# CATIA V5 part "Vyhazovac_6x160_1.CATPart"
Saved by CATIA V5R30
Part number: Vyhazovac_6x160_1
Nomenclature: E1710/6x160
Description: MEUSBURGER
Property "Material": "1.221"
Publications: "__DrillHole", "Base"
Bounding box of the stored display mesh (mm): x -5.992 to 5.992, y -5.992 to 5.992, z 0 to 156.5
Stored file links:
  E:\Bakalarka\Model\Forma_v7\Vyhazovac_6x160_1.CATPart
  E:\dev\MoldDesign\intel_a\startup\components\MoldCatalog\Ejector\Meusburger\Ejector_E1710\TableE1710.txt
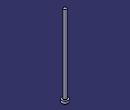
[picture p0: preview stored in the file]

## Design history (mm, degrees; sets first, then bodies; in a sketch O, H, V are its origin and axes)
Parameters
  Ref = "E1710/6x160" {design table}
  D1 = 6 mm {design table}
  D3 = 12 mm {design table}
  L = 160 mm {design table}
  L3 = 5 mm {design table}
  R = 0.5 mm {design table}
  k_d3 = 13 mm {design table}
  k_d1 = 6.2 mm {design table}
  k_F = 0.5 mm {design table}
  kl = 17 mm {design table}
  Mat = "1.221" {design table}
  HeatTreat = "ISO6751" {design table}
  Offset_Parting = 10 mm
  Anti_Rotation = "Normal"
  Anti_Rotation_D = 3.5 mm
  Anti_Rotation_D_Icut = 3.5 mm
  Add_Length_L = 1.8377 mm
  Add_Length_D3 = 0 mm
  SupplierRef = "Meusburger 2017"
  BmpRef = "F_MldEjectorD1"
  DrillHole_Length = 225 mm
  ValidationTest = false
  Anti_Rotation_D_min = 3.5 mm {= OffSet_D1 /2}
  Anti_Rotation_D_max = 5.925 mm {= D3/2-0.075mm}
  Anti_Rotation_D_ref = 3.5 mm {= Anti_Rotation_D}
  Anti_Rotation_D_Icut_ref = 3.5 mm {= Anti_Rotation_D_Icut}
  Anti_Rotation_Ref_Icut = 2.3246 mm
  Offset_L = 20 mm
  D = 6 mm {= D1}
  OffSet_D1 = 7 mm {= D1+2*R}
  OffSet_D3 = 13 mm {= D3+1mm}
  XG_Split = -80 mm
  YG_Split = -12 mm
  ZG_Split = -198 mm
  DirX_Split = 0 mm
  DirY_Split = 0 mm
  DirZ_Split = 1 mm
Set1 "BaseBody"
  Point1 "Base": (0, 0, 0)
  Plane1: type Offset, RefPlane xy-plane, Offset 225 {= DrillHole_Length}, reversed
  Sketch1 "Sketch.2" on xy-plane, origin (0, 0, 0), H (1, 0, 0), V (0, 1, 0)
    point P1 (-0.46, 1.1623)
    point P2 (0.46, 1.1623)
    construction line L1 (-0.46, 1.1623) -> (0.46, 1.1623)
    point P3 (0.46, -1.1623)
    line L2 (0.46, -1.1623) -> (0.46, 1.1623)
    point P4 (-0.46, -1.1623)
    construction line L3 (0.46, -1.1623) -> (-0.46, -1.1623)
    line L4 (-0.46, 1.1623) -> (-0.46, -1.1623)
    point P5 (-0.21, 1.1623)
    arc A1 centre (-0.21, 1.1623) radius 0.25 from (-0.21, 1.4123) to (-0.46, 1.1623) ccw
    point P7 (0.21, 1.1623)
    point P8 (0.21, 1.4123)
    arc A2 centre (0.21, 1.1623) radius 0.25 from (0.46, 1.1623) to (0.21, 1.4123) ccw
    line L5 (-0.21, 1.4123) -> (0.21, 1.4123)
    point P9 (-0.46, -1.1623)
    arc A3 centre (-0.21, -1.1623) radius 0.25 from (-0.46, -1.1623) to (-0.21, -1.4123) ccw
    point P11 (0.21, -1.4123)
    line L6 (-0.21, -1.4123) -> (0.21, -1.4123)
    point P12 (0.46, -1.1623)
    arc A4 centre (0.21, -1.1623) radius 0.25 from (0.21, -1.4123) to (0.46, -1.1623) ccw
    point P14 (-0.46, 1.1623)
    point P15 (-0.46, -1.1623)
    point P16 (0.46, 1.1623)
    point P17 (0.46, -1.1623)
    reference projected circle E1 centre (0, 0) radius 1.25 from edge [face of Shaft1 from Sketch2.L3 | face of Shaft1 from Sketch2.L4]
    reference projected circle E2 centre (0, 0) radius 1.25 from edge [face of Shaft1 from Sketch2.L3 | face of Shaft1 from Sketch2.L4]
    reference projected circle E3 centre (0, 0) radius 1.25 from edge [face of Shaft1 from Sketch2.L3 | face of Shaft1 from Sketch2.L4]
    reference projected circle E4 centre (0, 0) radius 1.25 from edge [face of Shaft1 from Sketch2.L3 | face of Shaft1 from Sketch2.L4]
    point P18 (-0.46, -1.1623)
    point P19 (-0.21, -1.4123)
    point P20 (0.21, -1.4123)
    point P21 (0.46, -1.1623)
    point P22 (-0.21, -1.4123)
    point P23 (0.21, -1.4123)
    distance P14 P15 = 2.3246 (reference)
    distance P16 P17 = 2.3246 (reference)
    distance L1 P14 = 0 (reference)
    radius A1 = 3
    distance L4 V = 3.51
    distance L2 V = 5.935
    distance L5 L6 = 12
    horizontal: L1 H, L3 H, L5 H
    vertical: L2 V, L4 V
    coincidence: P5 L1, P7 L1, P3 P12, P14 L4, P15 L4, P16 L2, P17 L2, P14 E1, P15 E2, P16 E3, P17 E4, P3 P21, P4 P18, P20 P23, P19 P22
    tangency: A1 L4, A2 L2, A2 L5, A1 L5
    symmetry: P1 P9 H, A1 A3 H, P8 P11 H, L5 L6 H, P2 P12 H, A2 A4 H
  DatumSurface1
Body1 "PartBody" (main body)
  Sketch2 "Sketch.1" on zx-plane, origin (0, 0, 0), H (-1, 0, 0), V (0, 0, 1)
    point P1 (0, 160)
    line L1 (3, 160) -> (0, 160)
    line L2 (3, 5) -> (3, 160)
    line L3 (6, 5) -> (3, 5)
    line L4 (6, 0) -> (6, 5)
    point P5 (0, 0)
    line L5 (0, 0) -> (6, 0)
    point P6 (0, 160)
    axis line L6 (0, 160) -> (0, 0)
    point P7 (0, 0)
    point P8 (3, 5)
    point P9 (3, 5)
    line L7 (0, 160) -> (0, 0)
    distance L5 L3 = 5 {= L3}
    distance L5 L1 = 160 {= L}
    distance L2 L6 = 3 {= D1 /2}
    distance L4 L6 = 6 {= D3 /2}
    coincidence: L6 P5, P1 L6, L5 H, L6 V, P7 O, P6 P1, P8 P9
    vertical: L2 V, L7 V
    horizontal: L1 H
  Shaft1 "Shaft.1": profile Sketch2, axis Sketch2.L6, angle 360
  Pocket1 "Pocket.1": profile Sketch1, direction (0, 0, 1), length 6, outer side, deactivated
  Pocket2 "Pocket.2": profile Sketch1, direction (0, 0, 1), length 6, outer side, deactivated
  Fillet1: radius 0.5 {= R}, on edge [face of Shaft1 from Sketch2.L2 | face of Shaft1 from Sketch2.L3]
  Pocket3: profile face of Shaft1 from Sketch2.L1, direction along face of Shaft1 from Sketch2.L1 reversed, up to face of DatumSurface1
Body2 "__DrillHole"
  Sketch3 "Sketch.3" on face of Shaft1, origin (0, 0, 0), H (1, 0, 0), V (0, -1, 0)
    point P1 (0, 0)
    reference projected point E1 (0, 0) from Point1
    coincidence: E1 P1
  Hole1 "Hole.1": placed by Sketch3, at (0, 0, 0) direction (0, 0, 1), diameter 7 {= OffSet_D1}, depth 140 {= L-Offset_L}
  Sketch4 "Sketch.4" on face of Shaft1, origin (0, 0, 0), H (1, 0, 0), V (0, -1, 0)
    point P1 (0, 0)
    reference projected point E1 (0, 0) from Point1
    coincidence: E1 P1
  Hole2 "Hole.2": placed by Sketch4, at (0, 0, 0) direction (0, 0, 1), diameter 6 {= D1}, depth 160 {= L}
  Sketch5 "Sketch.5" on face of Shaft1 from Sketch2.L3, origin (0, 0, 5), H (1, 0, 0), V (0, 1, 0)
    point P1 (0, 0)
    reference projected point E1 (0, 0) from Point1
    coincidence: E1 P1
  Hole3 "Hole.3": placed by Sketch5, at (0, 0, 5) direction (0, 0, -1), diameter 13 {= OffSet_D3}, depth 230 {= L3 +DrillHole_Length}
  Chamfer1: length 0.5 {= k_F}, angle 45, on edge [face of Hole1 | face of Hole3]
  Body3 "__Body.1"
    Pocket4 "Pocket.3": profile Sketch1, direction (0, 0, -1), length 225, opposite side length 5, deactivated
  Assemble1: tool Body3
  Chamfer2: length 0.5 {= k_F}, angle 45, on edge [start face of Pocket4 | face of Hole1], deactivated
  Body4 "__Body.2"
    Pocket5 "Pocket.4": profile Sketch1, direction (0, 0, -1), length 225, opposite side length 5, deactivated
  Assemble2: tool Body4
  Chamfer3: length 0.5 {= k_F}, angle 45, on edge [start face of Pocket5 | face of Hole1], deactivated
Relations
  design table "TableE1710", configuration 254, drives Ref, D1, D3, L, L3, R, k_d3, k_d1, k_F, kl, Mat, HeatTreat
  Offset_L = 20mm (deactivated)
  rule "Cut_Head_rule":
    let sketch_cut (length)
    let PartBody_Pocket_Sketch (Boolean)
    let I_PartBody_Pocket (Boolean)
    let D_PartBody_Pocket (Boolean)
    let N_DrillHole_Hole (Boolean)
    let N_DrillHole_Hole_Sketch (Boolean)
    let I_DrillHole_Pocket (Boolean)
    let D_DrillHole_Pocket (Boolean)
    /* --------------------------------------------------------------------------------------*/
    if Anti_Rotation =="Normal"
    {
    	sketch_cut=Anti_Rotation_D_max
    	PartBody_Pocket_Sketch = false
    	I_PartBody_Pocket = false
    	D_PartBody_Pocket = false
    	N_DrillHole_Hole = true
    	N_DrillHole_Hole_Sketch = true
    	I_DrillHole_Pocket = false
    	D_DrillHole_Pocket = false
    	Chamfer1.Activity= true
    	Chamfer2.Activity= false
    	Chamfer3.Activity= false
    }
    if Anti_Rotation == "I_Cut"
    {
    	sketch_cut=Anti_Rotation_D_Icut_ref
    	PartBody_Pocket_Sketch = true
    	I_PartBody_Pocket = true
    	D_PartBody_Pocket = false
    	N_DrillHole_Hole = false
    	N_DrillHole_Hole_Sketch = false
    	I_DrillHole_Pocket = true
    	D_DrillHole_Pocket = false
    	Chamfer1.Activity= false
    	Chamfer2.Activity= true
    	Chamfer3.Activity= false
    }
    if Anti_Rotation =="D_Cut"
    {
    	sketch_cut=Anti_Rotation_D_max
    	PartBody_Pocket_Sketch = true
    	I_PartBody_Pocket = false
    	D_PartBody_Pocket = true
    	N_DrillHole_Hole = false
    	N_DrillHole_Hole_Sketch = false
    	I_DrillHole_Pocket = false
    	D_DrillHole_Pocket = true
    	Chamfer1.Activity= false
    	Chamfer2.Activity= false
    	Chamfer3.Activity= true
    }
    /* --------------------------------------------------------------------------------------*/
    Sketch1.distance(L2 V) = sketch_cut+0.01mm
    Sketch1.distance(L4 V) =Anti_Rotation_D_ref+0.01mm
    Sketch1.radius(A1) =D/2
    Pocket4.FirstLimit.Depth = DrillHole_Length
    Pocket5.FirstLimit.Depth = DrillHole_Length
    Pocket1.FirstLimit.Depth = L3+1mm
    Pocket2.FirstLimit.Depth = L3+1mm
    Pocket4.SecondLimit.Depth = L3
    Pocket5.SecondLimit.Depth =L3
    Pocket1.Activity = I_PartBody_Pocket
    Pocket2.Activity = D_PartBody_Pocket
    Sketch1.Activity =PartBody_Pocket_Sketch
    Hole3.Activity= N_DrillHole_Hole
    Sketch5.Activity = N_DrillHole_Hole_Sketch
    Pocket4.Activity = I_DrillHole_Pocket
    Pocket5.Activity  = D_DrillHole_Pocket
  rule "Anti_Rotation_Icut_constrain":
    let Ref1(length)
    let Ref2(length)
    let Ref3(length)
    let Diam1(length)
    let Diam2(length)
    let Add_Length_Lmin (length)
    Ref1=Sketch1.distance(P14 P15)
    Ref2=Sketch1.distance(P16 P17)
    Diam1=D
    Diam2=D3
    /* --------------------------------------------------------------------*/
    if Ref1 >Ref2
    	Anti_Rotation_Ref_Icut = Ref1
    else
    	Anti_Rotation_Ref_Icut  =Ref2
    Add_Length_D3 .InferiorRange=Anti_Rotation_Ref_Icut /2+Diam1/2 -Diam2/2
    if Add_Length_D3 .InferiorRange<0mm
    	Add_Length_D3 .InferiorRange=0mm
    if ValidationTest == "true"
    	Ref3   = 2*Add_Length_L +Anti_Rotation_Ref_Icut  +2*Diam1/2
    else
    	Ref3  =Diam2+2*Add_Length_D3
    if Ref3 <Diam2
    {
    	Ref3 =Diam2
    }
    /* --------------------------------------------------------------------*/
    Sketch1.distance(L5 L6) = Ref3
    Add_Length_L .InferiorRange=Diam2/2-Anti_Rotation_Ref_Icut/2-Diam1/2
    Add_Length_Lmin=Diam2/2-Anti_Rotation_Ref_Icut/2-Diam1/2
    if Add_Length_Lmin<0mm
    	Add_Length_L .InferiorRange=0mm
    else
    	Add_Length_L .InferiorRange=Add_Length_Lmin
